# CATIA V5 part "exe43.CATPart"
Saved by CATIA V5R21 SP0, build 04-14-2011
Part number: exe43
Bounding box of the stored display mesh (mm): x -250 to 250, y -30 to 30, z -130.902 to 37
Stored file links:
  C:\Users\amir\Desktop\exe43.CATPart
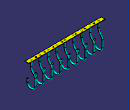
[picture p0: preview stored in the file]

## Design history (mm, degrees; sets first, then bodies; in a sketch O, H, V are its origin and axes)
Body1 (main body)
  Sketch1 on yz-plane, origin (0, 0, 0), H (0, 1, 0), V (0, 0, 1)
    point P1 (0, 35)
    line L1 (0, 35) -> (0, 0)
    line L2 (25, -55.9017) -> (25, -100.9017)
    arc A1 centre (0, -100.9017) radius 25 from (25, -100.9017) to (-25, -100.9017) cw
    point P4 (0, -100.9017)
    arc A2 centre (50, 0) radius 50 from (0, 0) to (16.6667, -37.2678) ccw
    point P6 (50, 0)
    arc A3 centre (0, -55.9017) radius 25 from (16.6667, -37.2678) to (25, -55.9017) cw
    point P8 (0, -55.9017)
    line L3 (-25, -100.9017) -> (-25, -80.9017)
    length L1 = 35
    radius A2 = 50
    radius A3 = 25
    distance P8 P4 V = 45
    radius A1 = 25
    length L3 = 20
    coincidence: P1 V, P8 L1, P6 H
    vertical: L1 V, L2 V, L3 V
    tangency: A1 L2, A3 L2, A2 A3, L3 A1
  Plane1: type Normal, Curve Sketch1
  Sketch2 on Plane1, origin (0, 0, -78.6315), H (1, 0, 0), V (0, 1, 0)
    circle A1 centre (0, 25) radius 5
    point P1 (0, 25)
    reference projected point E1 (0, 25) from Sketch1.L2
    radius A1 = 5
    coincidence: P1 V, P1 E1
  Rib1: profile Sketch2, centre curve Sketch1
  Sketch3 on face of Rib1, origin (0, 0, 35), H (1, 0, 0), V (0, 1, 0)
    line L1 (250, 12.5) -> (250, -12.5)
    line L2 (250, -12.5) -> (-250, -12.5)
    line L3 (-250, -12.5) -> (-250, 12.5)
    line L4 (-250, 12.5) -> (250, 12.5)
    length L3 = 25
    length L4 = 500
    vertical: L1 V, L3 V
    horizontal: L2 H, L4 H
    equidistance: L1 L3 O, L2 L4 O
  Pad1: profile Sketch3, direction (0, 0, 1), length 2
  RectPattern1: of Rib1, direction 1 instances 5, spacing 55, along face of Pad1 from Sketch3.L2
  RectPattern2: of Rib1, direction 1 instances 5, spacing 55, along face of Pad1 from Sketch3.L4
  Sketch4 on start face of Pad1, origin (-186.6038, 4.5739, 35), H (1, 0, 0), V (0, -1, 0)
    point P1 (-3.3962, 4.5739)
    reference projected line E1 (-63.3962, -7.9261) -> (-63.3962, 17.0739) from edge [start face of Pad1 | face of Pad1 from Sketch3.L3]
    reference projected line E2 (436.6038, -7.9261) -> (-63.3962, -7.9261) from edge [start face of Pad1 | face of Pad1 from Sketch3.L4]
    distance P1 E1 = 60
    distance P1 E2 = 12.5
  Hole1: placed by Sketch4, at (-190, 0, 35) direction (0, 0, 1), diameter 5, depth 10, counterbore diameter 8, counterbore depth 1
  RectPattern3: of Hole1, direction 1 instances 3, spacing 60, along start face of Pad1
  Sketch5 on start face of Pad1, origin (181.984, 3.7798, 35), H (1, 0, 0), V (0, -1, 0)
    point P1 (8.016, 3.7798)
    reference projected line E1 (68.016, 16.2798) -> (68.016, -8.7202) from edge [start face of Pad1 | face of Pad1 from Sketch3.L1]
    reference projected line E2 (68.016, -8.7202) -> (-431.984, -8.7202) from edge [start face of Pad1 | face of Pad1 from Sketch3.L4]
    distance P1 E1 = 60
    distance P1 E2 = 12.5
  Hole2: placed by Sketch5, at (190, 0, 35) direction (0, 0, 1), diameter 5, depth 10, counterbore diameter 8, counterbore depth 1
  RectPattern4: of Hole2, direction 1 instances 4, spacing 57, along start face of Pad1 reversed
